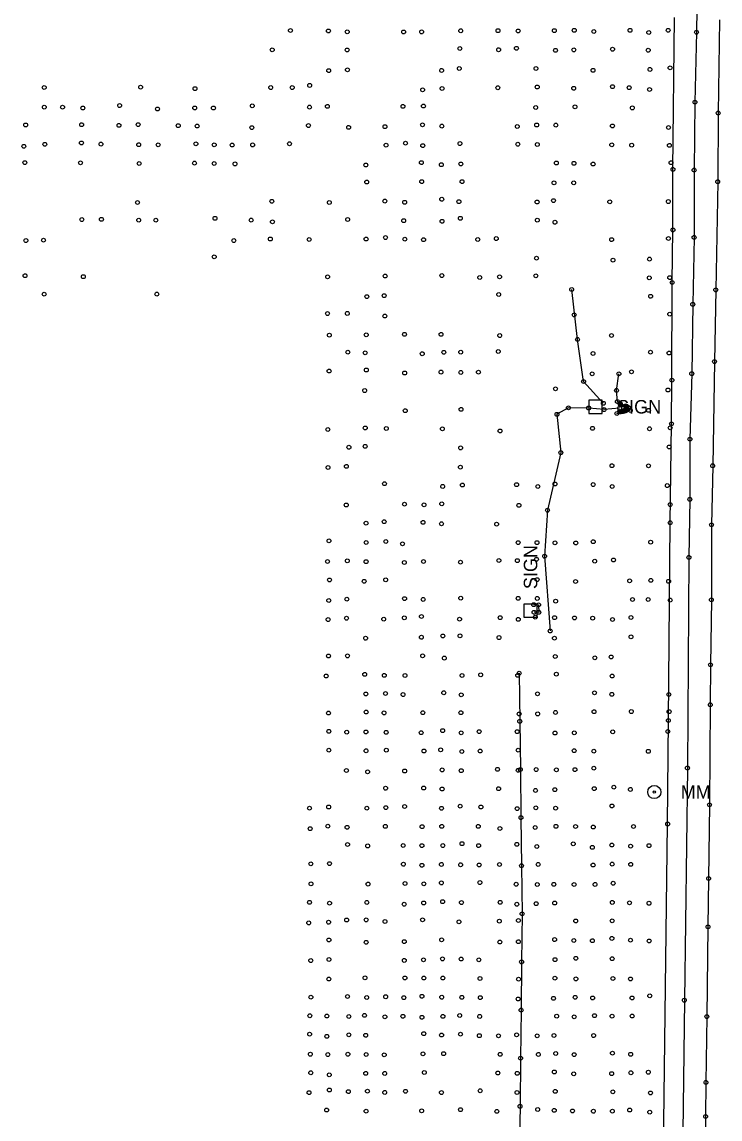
# Model space of a CAD drawing. Extents: x 20503438 to 20508873, y 7964251 to 7984667.
# Drawn here: x 20506243 to 20506606, y 7967935 to 7968505 of the extents above; entities that cross this region are included whole.
import ezdxf

# ---------------------------------------------------------------- set-up
doc = ezdxf.new("R2010")
doc.units = 0
for name, color, linetype in [('SurBreakLine', 7, 'Continuous'), ('SurConcreteSlab', 7, 'Continuous'), ('SurDrainageArrowDown', 7, 'Continuous'), ('SurDrainageArrowUp', 7, 'Continuous'), ('SurEdgeRoadPaved', 7, 'Continuous'), ('SurEdgeShoulderPaved', 7, 'Continuous'), ('SurMiscStructureLine', 7, 'Continuous'), ('SurPointsNonDTM', 7, 'Continuous'), ('SurRoadPoints', 7, 'Continuous'), ('SurSurveyPoints', 7, 'Continuous')]:
    doc.layers.add(name, color=color, linetype=linetype)

msp = doc.modelspace()

# ---------------------------------------------------------------- linework, layer by layer
at = {"layer": 'SurBreakLine'}
for points in [[(20506605.63, 7968505.56), (20506604.86, 7968457.2), (20506604.64, 7968421.53), (20506603.62, 7968365.33), (20506602.99, 7968328.08), (20506602.03, 7968273.99), (20506601.4, 7968243.29), (20506601.35, 7968204.34), (20506600.91, 7968170.61), (20506600.78, 7968149.85), (20506600.37, 7968097.89), (20506599.91, 7968059.63), (20506599.58, 7968034.48), (20506599, 7967987.85), (20506598.52, 7967953.67), (20506598.35, 7967935.98), (20506597.81, 7967884.63)], [(20506552.24, 7968301.11), (20506555.19, 7968302.08), (20506556.93, 7968302.55), (20506557.89, 7968303.22), (20506558.39, 7968304.06), (20506557.47, 7968304.82), (20506553.82, 7968306.43), (20506552.51, 7968307.31), (20506552.04, 7968313.13), (20506553.31, 7968321.71)]]:
    msp.add_lwpolyline(points, dxfattribs=at)
at = {"layer": 'SurConcreteSlab'}
msp.add_lwpolyline([(20506553.67, 7968302.17), (20506556.23, 7968302.79), (20506557.2, 7968303.37), (20506557.18, 7968304.44), (20506554.04, 7968305.9), (20506554.07, 7968306.17), (20506556.7, 7968305.07), (20506557.36, 7968304.58), (20506557.31, 7968303.9), (20506557.3, 7968303.45), (20506556.49, 7968302.68), (20506553.97, 7968301.88)], close=True, dxfattribs=at)
at = {"layer": 'SurDrainageArrowDown'}
for points in [[(20506553.67, 7968303.84), (20506545.61, 7968303.17), (20506537.61, 7968303.99), (20506527.08, 7968304.08), (20506521.11, 7968300.71), (20506523.12, 7968280.8), (20506516.18, 7968250.89), (20506514.7, 7968226.99), (20506517.59, 7968188.17)], [(20506501.5, 7968166.24), (20506501.8, 7968141.24), (20506502.11, 7968116.24), (20506502.42, 7968091.24), (20506502.72, 7968066.25), (20506503.01, 7968041.25), (20506502.75, 7968016.25), (20506502.49, 7967991.25), (20506502.23, 7967966.25), (20506501.94, 7967941.26), (20506501.49, 7967916.26)]]:
    msp.add_lwpolyline(points, dxfattribs=at)
at = {"layer": 'SurDrainageArrowUp'}
msp.add_lwpolyline([(20506545.21, 7968306.43), (20506534.95, 7968317.76), (20506531.8, 7968339.61), (20506528.77, 7968365.52)], dxfattribs=at)
at = {"layer": 'SurEdgeRoadPaved'}
msp.add_lwpolyline([(20506594.11, 7968535.15), (20506593.63, 7968499.17), (20506592.81, 7968462.84), (20506592.37, 7968427.56), (20506592.37, 7968392.62), (20506591.68, 7968357.85), (20506591.16, 7968321.83), (20506590.2, 7968287.8), (20506590.16, 7968256.55), (20506589.68, 7968226.38), (20506588.91, 7968116.99), (20506587.31, 7967996.36), (20506586.08, 7967886.56), (20506584.82, 7967803.95), (20506584.24, 7967753.89), (20506584.17, 7967748.01), (20506583.28, 7967668.66), (20506583.09, 7967656.74), (20506582.35, 7967604), (20506581.63, 7967561.97), (20506579.37, 7967345.44)], dxfattribs=at)
at = {"layer": 'SurEdgeShoulderPaved'}
msp.add_lwpolyline([(20506569.41, 7967351.99), (20506570.49, 7967465.47), (20506571.98, 7967587.39), (20506573.16, 7967664.08), (20506573.98, 7967730.71), (20506574.35, 7967759.63), (20506574.69, 7967793.52), (20506575.16, 7967825.3), (20506575.73, 7967865.88), (20506575.8, 7967891.16), (20506576.39, 7967918.66), (20506578.61, 7968087.9), (20506579.01, 7968141.69), (20506579.91, 7968244.38), (20506580.61, 7968295.76), (20506580.85, 7968318.42), (20506580.98, 7968369.15), (20506581.39, 7968396.47), (20506581.38, 7968427.94), (20506582.19, 7968506.89)], dxfattribs=at)
at = {"layer": 'SurMiscStructureLine'}
msp.add_lwpolyline([(20506509.06, 7968201.85), (20506511.58, 7968201.73), (20506511.71, 7968197.84), (20506509.23, 7968197.89)], dxfattribs=at)
at = {"layer": 'SurPointsNonDTM'}
for centre in [(20506509.06, 7968201.85), (20506511.58, 7968201.73), (20506509.23, 7968197.89), (20506511.71, 7968197.84)]:
    msp.add_circle(centre, 1, dxfattribs=at)
at = {"layer": 'SurRoadPoints'}
for points in [[(20506541.18, 7968301.2), (20506541.18, 7968301.2), (20506544.61, 7968301.2), (20506544.61, 7968308.06), (20506537.75, 7968308.06), (20506537.75, 7968301.2), (20506541.18, 7968301.2)], [(20506510.83, 7968198.73), (20506510.83, 7968198.73), (20506510.83, 7968202.16), (20506503.97, 7968202.16), (20506503.97, 7968195.3), (20506510.83, 7968195.3), (20506510.83, 7968198.73)]]:
    msp.add_lwpolyline(points, dxfattribs=at)
for radius in [3.43, 0.571]:
    msp.add_circle((20506571.7, 7968104.51), radius, dxfattribs=at)
at = {"layer": 'SurSurveyPoints'}
for centre in [(20506382.66, 7968500.05), (20506402.39, 7968499.85), (20506412.18, 7968499.39), (20506441.46, 7968499.32), (20506450.81, 7968499.34), (20506471.12, 7968499.94), (20506490.49, 7968500), (20506500.98, 7968499.84), (20506519.76, 7968500.01), (20506530.11, 7968500.16), (20506540.29, 7968499.54), (20506559.09, 7968500.16), (20506568.82, 7968499.03), (20506578.93, 7968500.2), (20506593.63, 7968499.17), (20506373.21, 7968490.02), (20506412.12, 7968489.98), (20506470.66, 7968490.73), (20506490.82, 7968490.08), (20506500.07, 7968490.83), (20506520.38, 7968489.77), (20506529.89, 7968490), (20506550.02, 7968490.34), (20506568.54, 7968489.82), (20506402.56, 7968479.23), (20506412.27, 7968479.67), (20506461.19, 7968479.33), (20506470.38, 7968480.32), (20506510.21, 7968480.32), (20506539.87, 7968479.39), (20506569.44, 7968479.86), (20506579.9, 7968480.68), (20506254.75, 7968470.47), (20506304.83, 7968470.63), (20506333.08, 7968469.9), (20506372.41, 7968470.43), (20506383.6, 7968470.43), (20506392.64, 7968471.55), (20506451.34, 7968469.28), (20506461.44, 7968469.93), (20506490.39, 7968470.34), (20506510.88, 7968470.72), (20506529.83, 7968470.05), (20506549.99, 7968470.91), (20506558.61, 7968470.38), (20506569.24, 7968469.42), (20506293.91, 7968461.08), (20506362.84, 7968460.96), (20506401.86, 7968460.66), (20506441.11, 7968460.66), (20506451.75, 7968460.84), (20506530.5, 7968460.42), (20506592.81, 7968462.84), (20506254.77, 7968460.23), (20506264.28, 7968460.23), (20506274.81, 7968459.81), (20506313.58, 7968459.3), (20506332.94, 7968459.84), (20506342.65, 7968459.81), (20506392.54, 7968460.29), (20506510.1, 7968460.05), (20506560.29, 7968459.87), (20506604.86, 7968457.2), (20506245.12, 7968451.02), (20506274.18, 7968451.13), (20506293.57, 7968450.8), (20506303.57, 7968451.19), (20506324.37, 7968450.63), (20506334.2, 7968450.44), (20506362.61, 7968449.62), (20506392.01, 7968450.69), (20506412.89, 7968449.76), (20506431.76, 7968450.11), (20506451.3, 7968451.06), (20506461.32, 7968450.42), (20506500.52, 7968450.22), (20506510.57, 7968450.98), (20506520.52, 7968450.94), (20506549.94, 7968450.5), (20506579.06, 7968449.72), (20506244.17, 7968439.93), (20506255.05, 7968440.97), (20506274.08, 7968441.67), (20506284.23, 7968441.07), (20506303.83, 7968440.75), (20506313.93, 7968440.7), (20506333.55, 7968441.2), (20506343.07, 7968440.69), (20506352.36, 7968440.57), (20506363, 7968440.64), (20506382.19, 7968441.25), (20506432.35, 7968440.51), (20506442.42, 7968441.58), (20506451.41, 7968440.29), (20506470.72, 7968441.34), (20506500.78, 7968440.99), (20506510.92, 7968440.88), (20506549.59, 7968440.69), (20506559.95, 7968440.54), (20506579.52, 7968440.4), (20506244.69, 7968431.45), (20506273.59, 7968431.32), (20506304.09, 7968431.01), (20506332.82, 7968431.2), (20506343.04, 7968430.96), (20506353.85, 7968430.78), (20506421.86, 7968430.21), (20506450.7, 7968431.44), (20506461.06, 7968430.36), (20506471.19, 7968430.76), (20506520.82, 7968431.26), (20506529.94, 7968431.08), (20506539.89, 7968430.71), (20506580.4, 7968431.4), (20506581.38, 7968427.94), (20506592.37, 7968427.56), (20506422.3, 7968421.36), (20506450.87, 7968421.58), (20506471.81, 7968421.57), (20506519.59, 7968420.97), (20506529.84, 7968420.94), (20506604.64, 7968421.53), (20506303.23, 7968410.75), (20506373, 7968411.37), (20506402.86, 7968410.72), (20506431.7, 7968411.47), (20506442.01, 7968410.85), (20506461.27, 7968412.42), (20506470.18, 7968411.16), (20506510.8, 7968410.98), (20506519.3, 7968411.71), (20506548.56, 7968411.09), (20506578.99, 7968411.22), (20506274.3, 7968401.86), (20506284.46, 7968402), (20506303.83, 7968401.53), (20506312.76, 7968401.57), (20506343.47, 7968402.51), (20506362.26, 7968401.59), (20506373.3, 7968400.68), (20506412.38, 7968401.93), (20506441.51, 7968401.31), (20506461.42, 7968400.98), (20506470.93, 7968402.54), (20506510.92, 7968401.53), (20506520.07, 7968400.47), (20506432.04, 7968392.51), (20506489.61, 7968391.99), (20506579.04, 7968392.06), (20506581.39, 7968396.47), (20506592.37, 7968392.62), (20506245.24, 7968390.96), (20506254.39, 7968391.18), (20506353.23, 7968390.96), (20506372.22, 7968391.77), (20506392.41, 7968391.53), (20506421.96, 7968391.75), (20506442.11, 7968391.67), (20506451.83, 7968391.41), (20506479.97, 7968391.53), (20506549.52, 7968391.46), (20506343.08, 7968382.54), (20506510.52, 7968381.81), (20506550.25, 7968380.76), (20506569.23, 7968381.33), (20506244.79, 7968372.69), (20506275.06, 7968372.2), (20506401.97, 7968372.1), (20506431.85, 7968372.52), (20506461.34, 7968372.77), (20506481.01, 7968371.8), (20506491.32, 7968372.14), (20506510.18, 7968372.62), (20506569.1, 7968371.61), (20506579.7, 7968371.71), (20506528.77, 7968365.52), (20506580.98, 7968369.15), (20506603.62, 7968365.33), (20506254.73, 7968363.09), (20506313.27, 7968363.16), (20506422.38, 7968361.84), (20506431.36, 7968362.34), (20506490.87, 7968362.95), (20506569.79, 7968362.01), (20506591.68, 7968357.85), (20506401.9, 7968353.04), (20506412.21, 7968353.12), (20506530.08, 7968352.35), (20506579.7, 7968352.7), (20506431.72, 7968351.75), (20506402.88, 7968341.8), (20506422.05, 7968342.01), (20506441.91, 7968342.26), (20506460.9, 7968342.22), (20506491.38, 7968341.61), (20506549.46, 7968341.66), (20506531.8, 7968339.61), (20506412.49, 7968332.98), (20506421.5, 7968332.64), (20506451.14, 7968332.17), (20506462.36, 7968332.94), (20506471.13, 7968332.99), (20506490.63, 7968333.33), (20506539.87, 7968332.28), (20506569.72, 7968332.99), (20506579.37, 7968332.53), (20506422.08, 7968323.74), (20506602.99, 7968328.08), (20506402.75, 7968323.19), (20506442.01, 7968322.18), (20506460.88, 7968322.64), (20506471.18, 7968322.47), (20506480.32, 7968322.58), (20506539.39, 7968321.75), (20506553.31, 7968321.71), (20506559.85, 7968322.75), (20506580.85, 7968318.42), (20506591.16, 7968321.83), (20506421.23, 7968313.04), (20506520.39, 7968313.93), (20506534.95, 7968317.76), (20506552.04, 7968313.13), (20506578.81, 7968313.34), (20506552.51, 7968307.31), (20506442.31, 7968302.59), (20506471.3, 7968303.28), (20506527.08, 7968304.08), (20506537.61, 7968303.99), (20506545.21, 7968306.43), (20506545.61, 7968303.17), (20506552.24, 7968301.11), (20506553.67, 7968303.84), (20506553.67, 7968302.17), (20506553.82, 7968306.43), (20506553.97, 7968301.88), (20506554.04, 7968305.9), (20506554.07, 7968306.17), (20506555.19, 7968302.08), (20506556.23, 7968302.79), (20506556.49, 7968302.68), (20506556.7, 7968305.07), (20506556.93, 7968302.55), (20506557.18, 7968304.44), (20506557.2, 7968303.37), (20506557.3, 7968303.45), (20506557.31, 7968303.9), (20506557.36, 7968304.58), (20506557.47, 7968304.82), (20506557.89, 7968303.22), (20506558.39, 7968304.06), (20506559.26, 7968302.71), (20506568.67, 7968302.76), (20506521.11, 7968300.71), (20506580.61, 7968295.76), (20506402.12, 7968292.84), (20506421.53, 7968293.64), (20506432.47, 7968293.32), (20506461.61, 7968293.18), (20506491.57, 7968292.06), (20506539.59, 7968293.43), (20506569.21, 7968293.21), (20506579.92, 7968293.71), (20506421.46, 7968284.08), (20506579.42, 7968283.76), (20506590.2, 7968287.8), (20506413.04, 7968283.6), (20506471.08, 7968283.26), (20506523.12, 7968280.8), (20506402.21, 7968273.07), (20506411.72, 7968273.67), (20506470.96, 7968273.23), (20506549.7, 7968274.01), (20506568.67, 7968273.97), (20506602.03, 7968273.99), (20506431.54, 7968264.67), (20506461.76, 7968263.25), (20506471.99, 7968263.96), (20506500.15, 7968264.18), (20506511.17, 7968263.23), (20506520.09, 7968264.51), (20506539.92, 7968264.22), (20506549.82, 7968263.19), (20506578.44, 7968263.69), (20506590.16, 7968256.55), (20506411.66, 7968253.61), (20506441.92, 7968254.04), (20506452.08, 7968253.71), (20506461.27, 7968254.22), (20506501.36, 7968253.42), (20506516.18, 7968250.89), (20506579.94, 7968253.83), (20506421.96, 7968244.14), (20506431.37, 7968244.91), (20506451.56, 7968244.57), (20506461.16, 7968243.86), (20506579.91, 7968244.38), (20506489.77, 7968243.62), (20506601.4, 7968243.29), (20506402.68, 7968234.99), (20506421.98, 7968234.12), (20506432.22, 7968234.62), (20506440.91, 7968233.44), (20506500.99, 7968234.06), (20506510.75, 7968234.06), (20506520.08, 7968233.98), (20506530.89, 7968233.89), (20506539.98, 7968234.53), (20506569.8, 7968234.3), (20506514.7, 7968226.99), (20506401.89, 7968224.25), (20506412.21, 7968224.63), (20506421.96, 7968224.17), (20506441.84, 7968223.72), (20506451.76, 7968224.25), (20506471.03, 7968223.92), (20506490.97, 7968224.75), (20506500.53, 7968224.71), (20506510.47, 7968225.42), (20506540.73, 7968224.45), (20506550.5, 7968225.05), (20506589.68, 7968226.38), (20506402.96, 7968214.67), (20506420.97, 7968213.99), (20506432.14, 7968214.74), (20506510.8, 7968214.85), (20506530.79, 7968213.89), (20506558.86, 7968214.19), (20506569.9, 7968214.44), (20506579.13, 7968213.96), (20506402.57, 7968204.02), (20506411.99, 7968204.67), (20506441.95, 7968204.98), (20506451.6, 7968204.56), (20506471.13, 7968205.23), (20506501, 7968205.13), (20506510.9, 7968205.08), (20506560.36, 7968204.54), (20506568.51, 7968204.53), (20506579.95, 7968204.21), (20506601.35, 7968204.34), (20506520.44, 7968203.63), (20506402.23, 7968194.1), (20506411.8, 7968194.79), (20506431.13, 7968194.33), (20506441.82, 7968195), (20506450.71, 7968195.71), (20506470.53, 7968194.31), (20506491.62, 7968195.09), (20506501.04, 7968194.2), (20506509.87, 7968195.37), (20506519.89, 7968195.09), (20506530.25, 7968194.93), (20506539.67, 7968194.85), (20506549.95, 7968194.13), (20506559.56, 7968195.19), (20506517.59, 7968188.17), (20506421.72, 7968184.4), (20506450.69, 7968184.91), (20506461.84, 7968185.58), (20506470.75, 7968185.67), (20506491.01, 7968184.75), (20506519.81, 7968184.45), (20506559.59, 7968185.1), (20506402.43, 7968175.18), (20506412.28, 7968175.22), (20506451.33, 7968175.25), (20506462.62, 7968174.09), (20506520.23, 7968174.9), (20506540.81, 7968174.2), (20506549.31, 7968174.67), (20506600.91, 7968170.61), (20506401.2, 7968164.78), (20506421.24, 7968165.63), (20506431.41, 7968165.11), (20506442.17, 7968165.07), (20506471.83, 7968165.03), (20506481.5, 7968165.39), (20506500.73, 7968165.1), (20506501.5, 7968166.24), (20506520.81, 7968165.74), (20506549.81, 7968164.76), (20506421.82, 7968155.45), (20506432.06, 7968155.71), (20506441.16, 7968155.14), (20506462.31, 7968156.08), (20506471.39, 7968155.01), (20506511.04, 7968155.53), (20506540.6, 7968156.01), (20506549.66, 7968155.26), (20506579.24, 7968155.19), (20506600.78, 7968149.85), (20506402.43, 7968145.54), (20506422.02, 7968146.06), (20506431.3, 7968145.61), (20506451.46, 7968145.72), (20506471.23, 7968145.72), (20506501.47, 7968145.06), (20506501.8, 7968141.24), (20506511.11, 7968145.1), (20506520.35, 7968145.86), (20506540.4, 7968146.22), (20506559.76, 7968146.31), (20506579.01, 7968141.69), (20506579.38, 7968146.26), (20506402.63, 7968136.03), (20506411.91, 7968135.6), (20506421.88, 7968135.73), (20506461.76, 7968136.41), (20506480.74, 7968135.9), (20506500.45, 7968135.87), (20506550.1, 7968135.79), (20506578.72, 7968135.94), (20506432.41, 7968135.53), (20506450.57, 7968135.32), (20506471.36, 7968135.25), (20506520.11, 7968135.15), (20506530.13, 7968135.25), (20506402.61, 7968126.25), (20506421.94, 7968125.95), (20506432.48, 7968126.24), (20506452.03, 7968125.83), (20506460.7, 7968126.46), (20506471.69, 7968125.58), (20506481.23, 7968125.8), (20506500.95, 7968126.28), (20506530.08, 7968125.97), (20506540.28, 7968125.71), (20506568.59, 7968125.65), (20506411.74, 7968115.68), (20506422.76, 7968115.01), (20506442.01, 7968115.45), (20506461.5, 7968116), (20506471.39, 7968115.6), (20506490.21, 7968116.3), (20506501, 7968115.81), (20506502.11, 7968116.24), (20506510.3, 7968116.18), (20506520.83, 7968116.07), (20506530.46, 7968116.16), (20506540.29, 7968116.91), (20506588.91, 7968116.99), (20506550.67, 7968107.05), (20506432.11, 7968106.49), (20506451.89, 7968106.59), (20506461.45, 7968106.08), (20506490.82, 7968106.24), (20506509.95, 7968105.34), (20506520.02, 7968105.73), (20506540.5, 7968106.3), (20506559.27, 7968105.87), (20506392.57, 7968096.14), (20506402.52, 7968096.73), (20506422.36, 7968096.11), (20506432.23, 7968096.41), (20506441.97, 7968097), (20506461.13, 7968096.08), (20506470.85, 7968097.15), (20506481.61, 7968096.74), (20506500.44, 7968095.9), (20506510.17, 7968096.3), (20506520.42, 7968096.12), (20506549.69, 7968097.28), (20506600.37, 7968097.89), (20506502.42, 7968091.24), (20506392.91, 7968085.48), (20506402.09, 7968086.77), (20506412.09, 7968086.2), (20506431.95, 7968086.67), (20506451.06, 7968086.53), (20506461.27, 7968086.68), (20506480.26, 7968086.66), (20506491.49, 7968085.54), (20506509.78, 7968086.09), (20506520.59, 7968086.69), (20506530.79, 7968086.59), (20506540, 7968086.32), (20506560.91, 7968086.62), (20506578.61, 7968087.9), (20506412.34, 7968077.27), (20506422.79, 7968076.52), (20506441.22, 7968076.73), (20506450.96, 7968076.68), (20506461.82, 7968076.7), (20506471.78, 7968077.68), (20506480.43, 7968076.67), (20506500.27, 7968077.34), (20506510.65, 7968076.21), (20506529.59, 7968077.61), (20506539.5, 7968075.75), (20506549.61, 7968076.98), (20506559.38, 7968076.39), (20506568.94, 7968076.67), (20506393.23, 7968067.19), (20506402.97, 7968067.33), (20506441.34, 7968067.01), (20506450.97, 7968066.46), (20506461.09, 7968066.91), (20506471.08, 7968066.73), (20506480.69, 7968066.63), (20506491.25, 7968066.9), (20506502.72, 7968066.25), (20506511.34, 7968066.91), (20506539.89, 7968066.58), (20506549.82, 7968067.08), (20506559.45, 7968066.94), (20506393.34, 7968056.82), (20506422.98, 7968056.7), (20506442.2, 7968057.02), (20506451.98, 7968056.85), (20506461.09, 7968057.31), (20506481.1, 7968057.48), (20506499.95, 7968056.61), (20506510.9, 7968056.48), (20506519.47, 7968056.57), (20506530.03, 7968056.51), (20506540.91, 7968056.52), (20506550.33, 7968057.13), (20506599.91, 7968059.63), (20506392.54, 7968047.22), (20506402.99, 7968046.76), (20506422.32, 7968047.17), (20506441.76, 7968046.23), (20506451.89, 7968046.89), (20506461.73, 7968047.58), (20506471.49, 7968047.1), (20506491.63, 7968047.21), (20506500.27, 7968046.22), (20506510.35, 7968046.53), (20506519.92, 7968046.84), (20506549.87, 7968047.18), (20506558.84, 7968046.97), (20506568.94, 7968046.74), (20506503.01, 7968041.25), (20506392.15, 7968036.54), (20506402.5, 7968036.88), (20506411.84, 7968038.04), (20506421.99, 7968038.09), (20506431.8, 7968037.25), (20506451.31, 7968038.1), (20506470.21, 7968037.07), (20506491.2, 7968037.41), (20506501.1, 7968037.76), (20506530.87, 7968037.56), (20506549.83, 7968037.6), (20506599.58, 7968034.48), (20506402.64, 7968027.69), (20506461.19, 7968027.75), (20506519.9, 7968027.87), (20506529.92, 7968027.37), (20506539.53, 7968027.27), (20506549.67, 7968028.48), (20506559.31, 7968027.58), (20506422.02, 7968026.47), (20506441.8, 7968026.82), (20506491.47, 7968026.6), (20506501.08, 7968026.77), (20506569.03, 7968027.15), (20506393.22, 7968016.97), (20506402.67, 7968017.55), (20506441.81, 7968017.05), (20506451.82, 7968017.34), (20506461.65, 7968017.83), (20506471.36, 7968017.77), (20506480.52, 7968017.37), (20506502.75, 7968016.25), (20506520.12, 7968017.46), (20506530.93, 7968018.17), (20506549.81, 7968017.94), (20506402.61, 7968007.37), (20506421.39, 7968008.03), (20506442.13, 7968007.94), (20506451.97, 7968007.9), (20506461.82, 7968007.9), (20506481.15, 7968007.64), (20506501.19, 7968007.34), (20506520.06, 7968007.8), (20506530.97, 7968007.44), (20506550.19, 7968007.63), (20506559.34, 7968007.42), (20506393.29, 7967997.97), (20506412.31, 7967998.28), (20506422.29, 7967997.76), (20506432.14, 7967998.18), (20506441.58, 7967997.7), (20506450.99, 7967998.41), (20506461.25, 7967997.92), (20506471.71, 7967997.88), (20506481.3, 7967997.73), (20506500.97, 7967997.01), (20506519.34, 7967997.36), (20506530.59, 7967997.89), (20506539.65, 7967997.56), (20506560.13, 7967997.55), (20506569.33, 7967998.68), (20506587.31, 7967996.36), (20506392.73, 7967988.31), (20506401.54, 7967988.14), (20506412.99, 7967987.92), (20506421.15, 7967988.49), (20506431.74, 7967987.77), (20506441.1, 7967988.03), (20506450.98, 7967987.52), (20506461.88, 7967987.97), (20506470.6, 7967988.41), (20506480.98, 7967987.96), (20506502.49, 7967991.25), (20506520.98, 7967988.07), (20506530.09, 7967987.76), (20506540.65, 7967988.34), (20506549.76, 7967988.11), (20506560.17, 7967988.14), (20506599, 7967987.85), (20506392.63, 7967978.75), (20506401.54, 7967977.61), (20506413, 7967978.4), (20506421.77, 7967978.15), (20506451.93, 7967978.99), (20506461.18, 7967978.29), (20506471, 7967978.76), (20506480.81, 7967977.97), (20506490.73, 7967977.89), (20506500.17, 7967978.41), (20506510.82, 7967977.9), (20506519.57, 7967978.02), (20506540.16, 7967978.01), (20506393, 7967968.31), (20506402.11, 7967968.14), (20506412.52, 7967968.32), (20506421.99, 7967968.18), (20506431.39, 7967968.01), (20506451.5, 7967968.52), (20506462.25, 7967968.6), (20506491.64, 7967968.28), (20506502.23, 7967966.25), (20506511.47, 7967968.22), (20506520.49, 7967968.72), (20506530.07, 7967968.12), (20506549.94, 7967968.85), (20506559.42, 7967968.3), (20506519.75, 7967959.12), (20506568.6, 7967958.96), (20506393.22, 7967958.69), (20506402.83, 7967957.63), (20506421.76, 7967958.36), (20506431.65, 7967958.35), (20506452.21, 7967958.82), (20506490.43, 7967958.57), (20506500.49, 7967958.41), (20506529.83, 7967958.15), (20506549.54, 7967958.24), (20506559.55, 7967958.69), (20506598.52, 7967953.67), (20506392.34, 7967948.37), (20506402.89, 7967949.73), (20506412.76, 7967948.91), (20506422.66, 7967949.12), (20506431.63, 7967948.48), (20506442.41, 7967949.08), (20506461.11, 7967948.41), (20506481.24, 7967949.34), (20506500.37, 7967948.47), (20506520.24, 7967949.01), (20506550.16, 7967948.77), (20506569.7, 7967948.21), (20506401.45, 7967939.32), (20506421.97, 7967938.74), (20506450.83, 7967938.94), (20506471.03, 7967939.52), (20506489.91, 7967938.63), (20506501.94, 7967941.26), (20506511.11, 7967939.63), (20506519.71, 7967939.15), (20506529.22, 7967938.86), (20506540.06, 7967938.71), (20506549.92, 7967938.73), (20506558.91, 7967939.33), (20506569.33, 7967938.23), (20506598.35, 7967935.98)]:
    msp.add_circle(centre, 1, dxfattribs=at)

# ---------------------------------------------------------------- texts
at = {"layer": 'SurRoadPoints'}
for s, rotation, p in [('SIGN', 360, (20506552.39, 7968301.13)), ('SIGN', 90, (20506510.9, 7968209.94)), ('MM', 360, (20506585.41, 7968101.01))]:
    msp.add_text(s, height=6.995, rotation=rotation, dxfattribs=at).set_placement(p)

doc.saveas('drawing.dxf')
